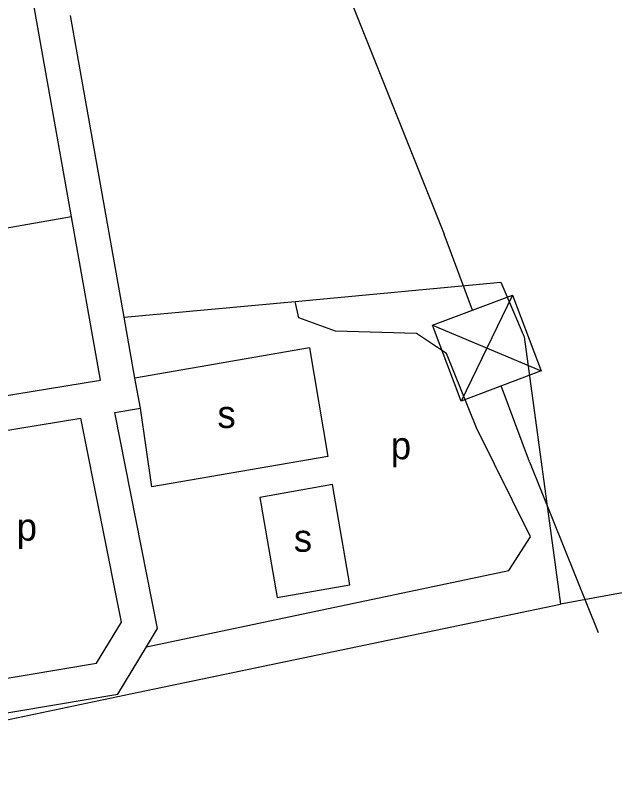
# Model space of a CAD drawing. Extents: x 162883 to 165538, y 383986 to 385172.
# Drawn here: x 164685.6 to 164773.2, y 384313.1 to 384426.2 of the extents above; entities that cross this region are included whole.
import ezdxf

# ---------------------------------------------------------------- set-up
doc = ezdxf.new("R2010")
doc.units = 0
for name, color, linetype in [('BLT_Basislijn', 7, 'Continuous'), ('BLT_Centroide', 7, 'Continuous'), ('BLT_Hoogspanningsmast_en_leidingen', 7, 'Continuous')]:
    doc.layers.add(name, color=color, linetype=linetype)

msp = doc.modelspace()

# ---------------------------------------------------------------- linework, layer by layer
at = {"layer": 'BLT_Basislijn'}
for p, q in [((164693.76, 384396.74), (164686.66, 384436.63)), ((164701.46, 384382.04), (164693.6, 384426.19)), ((164693.76, 384396.74), (164656.52, 384390.24)), ((164701.46, 384382.04), (164726.49, 384384.36)), ((164703.04, 384373.12), (164701.46, 384382.04)), ((164728.59, 384377.58), (164703.04, 384373.12)), ((164703.83, 384368.72), (164703.04, 384373.12)), ((164700.07, 384368.1), (164703.83, 384368.72)), ((164656.16, 384360.93), (164695.13, 384367.3)), ((164702.41, 384326.97), (164765.31, 384340.08)), ((164636.3, 384313.11), (164702.41, 384326.97))]:
    msp.add_line(p, q, dxfattribs=at)
for points in [[(164655.29, 384365.86), (164698.02, 384372.84), (164693.76, 384396.74)], [(164726.49, 384384.36), (164756.59, 384387.16), (164760, 384379.19), (164765.31, 384340.08)], [(164704.73, 384333.85), (164757.74, 384345.01), (164760.92, 384349.91), (164753.01, 384365.85), (164748.62, 384376.75), (164744.24, 384379.68), (164732.37, 384380), (164727.01, 384381.95), (164726.49, 384384.36)], [(164728.59, 384377.58), (164731.27, 384361.67), (164705.53, 384357.25), (164703.83, 384368.72)], [(164704.73, 384333.85), (164706.33, 384336.5), (164700.07, 384368.1)], [(164671, 384327.01), (164697.43, 384331.44), (164701.05, 384337.43), (164695.13, 384367.3)], [(164852.9, 384357.01), (164807.26, 384347.79), (164765.31, 384340.08)], [(164671.8, 384322.08), (164700.52, 384326.89), (164704.73, 384333.85)]]:
    msp.add_lwpolyline(points, dxfattribs=at)
msp.add_lwpolyline([(164721.32, 384355.7), (164723.84, 384341.03), (164734.48, 384342.9), (164731.96, 384357.58)], close=True, dxfattribs=at)
at = {"layer": 'BLT_Hoogspanningsmast_en_leidingen'}
for p, q in [((164705.94, 384500), (164748.28, 384394.2)), ((164752.44, 384383.09), (164748.28, 384394.2)), ((164746.58, 384380.9), (164758.3, 384385.29)), ((164758.3, 384385.29), (164750.75, 384369.79)), ((164758.3, 384385.29), (164762.46, 384374.18)), ((164750.75, 384369.79), (164746.58, 384380.9)), ((164746.58, 384380.9), (164762.46, 384374.18)), ((164762.46, 384374.18), (164750.75, 384369.79)), ((164760.77, 384360.88), (164756.61, 384371.99)), ((164760.77, 384360.88), (164770.82, 384335.93))]:
    msp.add_line(p, q, dxfattribs=at)

# ---------------------------------------------------------------- texts
at = {"layer": 'BLT_Centroide'}
for s, p in [('s', (164715.11, 384365.85)), ('p', (164740.47, 384361.28)), ('p', (164685.73, 384349.37)), ('s', (164726.29, 384347.74))]:
    msp.add_text(s, height=4, dxfattribs=at).set_placement(p)

doc.saveas('drawing.dxf')
